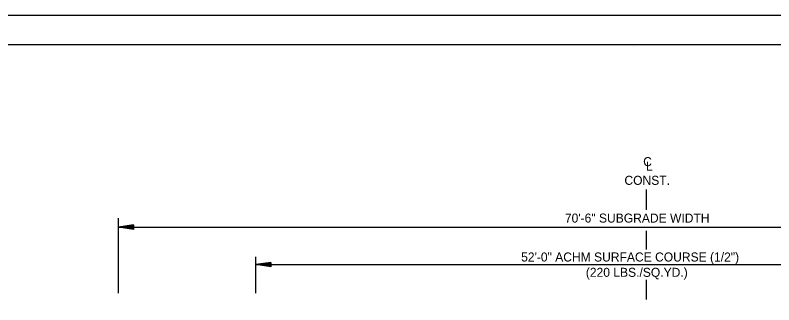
# Model space of a CAD drawing. Extents: x 1371763 to 1372860, y 385599 to 385872.
# Drawn here: x 1371804.7 to 1371855.1, y 385852.6 to 385871.8 of the extents above; entities that cross this region are included whole.
import ezdxf

# ---------------------------------------------------------------- set-up
doc = ezdxf.new("R2010")
doc.units = 0
doc.layers.add('R_Draft', color=7, linetype='Continuous')
doc.layers.add('R_No Plot', color=7, linetype='Continuous')

msp = doc.modelspace()

# ---------------------------------------------------------------- linework, layer by layer
at = {"layer": 'R_Draft'}
for p, q in [((1371846.684, 385858.892), (1371846.684, 385860.242)), ((1371811.547, 385853.344), (1371811.547, 385858.342)), ((1371812.547, 385857.892), (1371811.547, 385857.742)), ((1371812.547, 385857.867), (1371811.714, 385857.742)), ((1371812.547, 385857.841), (1371811.886, 385857.742)), ((1371812.547, 385857.892), (1371812.547, 385857.592)), ((1371811.547, 385857.742), (1371881.82, 385857.742)), ((1371812.547, 385857.592), (1371811.547, 385857.742)), ((1371812.547, 385857.617), (1371811.714, 385857.742)), ((1371812.547, 385857.642), (1371811.886, 385857.742)), ((1371812.547, 385857.816), (1371812.053, 385857.742)), ((1371812.547, 385857.667), (1371812.053, 385857.742)), ((1371812.547, 385857.79), (1371812.222, 385857.742)), ((1371812.547, 385857.693), (1371812.222, 385857.742)), ((1371812.547, 385857.765), (1371812.389, 385857.742)), ((1371812.547, 385857.718), (1371812.389, 385857.742)), ((1371846.684, 385856.242), (1371846.684, 385857.492)), ((1371820.68, 385853.344), (1371820.68, 385855.752)), ((1371821.68, 385855.392), (1371820.68, 385855.242)), ((1371821.68, 385855.367), (1371820.847, 385855.242)), ((1371821.68, 385855.341), (1371821.019, 385855.242)), ((1371821.68, 385855.316), (1371821.186, 385855.242)), ((1371821.68, 385855.392), (1371821.68, 385855.092)), ((1371820.68, 385855.242), (1371872.681, 385855.242)), ((1371821.68, 385855.092), (1371820.68, 385855.242)), ((1371821.68, 385855.117), (1371820.847, 385855.242)), ((1371821.68, 385855.142), (1371821.019, 385855.242)), ((1371821.68, 385855.167), (1371821.186, 385855.242)), ((1371821.68, 385855.29), (1371821.355, 385855.242)), ((1371821.68, 385855.193), (1371821.355, 385855.242)), ((1371821.68, 385855.265), (1371821.522, 385855.242)), ((1371821.68, 385855.218), (1371821.522, 385855.242)), ((1371846.684, 385852.928), (1371846.684, 385854.242))]:
    msp.add_line(p, q, dxfattribs=at)
at = {"layer": 'R_No Plot'}
for p, q in [((1371763.354, 385871.845), (1371930.021, 385871.845)), ((1371769.555, 385869.898), (1371927.645, 385869.898)), ((1371845.815, 385869.768), (1371845.815, 385869.768)), ((1371845.815, 385869.768), (1371845.815, 385869.768))]:
    msp.add_line(p, q, dxfattribs=at)
for points in [[(1371763.351, 385871.845), (1371930.021, 385871.845), (1371930.021, 385765.176), (1371763.351, 385765.176)], [(1371886.515, 385869.898), (1371896.325, 385869.898), (1371896.325, 385864.958), (1371904.381, 385864.958), (1371915.98, 385864.958), (1371916.041, 385850.88), (1371927.645, 385850.88), (1371927.645, 385767.168), (1371769.555, 385767.168), (1371769.555, 385869.898)]]:
    msp.add_lwpolyline(points, close=True, dxfattribs=at)

# ---------------------------------------------------------------- texts
at = {"layer": 'R_Draft'}
for s, p in [('C', (1371846.459, 385861.798)), ('L', (1371846.645, 385861.498)), ('CONST.', (1371845.21, 385860.554)), ('70\'-6" SUBGRADE WIDTH', (1371841.251, 385858.042)), ('52\'-0" ACHM SURFACE COURSE (1/2")', (1371838.34, 385855.452)), ('(220 LBS./SQ.YD.)', (1371842.644, 385854.432))]:
    msp.add_text(s, height=0.6, rotation=360, dxfattribs=at).set_placement(p)

doc.saveas('drawing.dxf')
